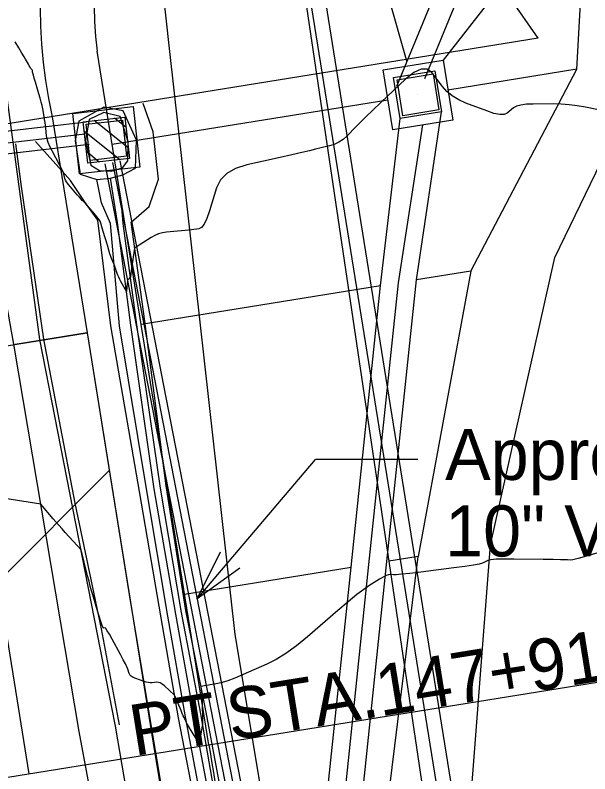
# Model space of a CAD drawing. Extents: x 2030588 to 2035216, y 462285 to 465007.
# Drawn here: x 2031264.56 to 2031296.08, y 464275.55 to 464317.16 of the extents above; entities that cross this region are included whole.
import ezdxf

# ---------------------------------------------------------------- set-up
doc = ezdxf.new("R2010")
doc.units = 0
for name, color, linetype in [('DR_P_Cells', 7, 'Continuous'), ('DR_P_Ditch', 7, 'Continuous'), ('DR_P_Drive_Pipe', 7, 'Continuous'), ('DR_X_Cells', 7, 'Continuous'), ('DR_X_Ditch', 7, 'Continuous'), ('DR_X_Storm_Sewer', 7, 'Continuous'), ('DT_P_Pavement_Surface', 7, 'Continuous'), ('DT_P_Slope_Break_Line', 7, 'Continuous'), ('DT_X_Contour_Minor', 7, 'Continuous'), ('GE_X_Alignment_100_Cardinal_Points', 7, 'Continuous'), ('GK_Drainage_Nodes', 7, 'Continuous'), ('MD_P_CONST_LIMITS', 7, 'Continuous'), ('MT_P_Temp_Road', 7, 'Continuous'), ('PV_P_EOP', 7, 'Continuous'), ('PV_P_Shoulder', 7, 'Continuous'), ('PV_X_EOP', 7, 'Continuous'), ('PV_X_Shoulder_Aggregate', 7, 'Continuous'), ('RW_X_Esmt_SH', 7, 'Continuous'), ('SV_X_Break_Lines', 7, 'Continuous'), ('SV_X_Text', 7, 'Continuous'), ('SV_X_Toe_of_Slope', 7, 'Continuous'), ('UT_X_Cable_TV', 7, 'Continuous'), ('UT_X_Electric', 7, 'Continuous'), ('UT_X_Telecom', 7, 'Continuous')]:
    doc.layers.add(name, color=color, linetype=linetype)

msp = doc.modelspace()

# ---------------------------------------------------------------- linework, layer by layer
at = {"layer": 'DR_P_Cells'}
for points in [[(2031284.745, 464314.169), (2031288.035, 464314.699), (2031288.566, 464311.409), (2031285.275, 464310.878)], [(2031285.315, 464313.748), (2031287.577, 464314.113), (2031287.942, 464311.851), (2031285.68, 464311.486)], [(2031285.509, 464313.617), (2031287.483, 464313.935), (2031287.802, 464311.961), (2031285.827, 464311.642)]]:
    msp.add_lwpolyline(points, close=True, dxfattribs=at)
at = {"layer": 'DR_P_Ditch'}
msp.add_lwpolyline([(2031284.892, 464242.767), (2031281.32, 464261.654), (2031283.968, 464287.035), (2031285.58, 464302.487), (2031286.92, 464311.143)], dxfattribs=at)
at = {"layer": 'DR_P_Drive_Pipe'}
for p, q in [((2031285.496, 464313.266), (2031292.582, 464330.451)), ((2031287.024, 464313.693), (2031293.738, 464329.975))]:
    msp.add_line(p, q, dxfattribs=at)
at = {"layer": 'DR_X_Cells'}
for p, q in [((2031270.759, 464309.885), (2031268.888, 464311.378)), ((2031270.633, 464311.009), (2031270.012, 464311.504)), ((2031270.297, 464309.231), (2031268.352, 464310.782)), ((2031269.172, 464309.104), (2031268.479, 464309.658)), ((2031269.479, 464309.004), (2031281.942, 464244.875)), ((2031270.297, 464309.163), (2031282.76, 464245.034))]:
    msp.add_line(p, q, dxfattribs=at)
for points in [[(2031268.089, 464308.458), (2031267.717, 464311.77), (2031271.029, 464312.143), (2031271.402, 464308.831)], [(2031268.549, 464309.034), (2031268.293, 464311.311), (2031270.57, 464311.567), (2031270.826, 464309.29)], [(2031268.677, 464309.195), (2031268.454, 464311.183), (2031270.441, 464311.406), (2031270.665, 464309.419)]]:
    msp.add_lwpolyline(points, close=True, dxfattribs=at)
for points in [[(2031268.463, 464311.299), (2031228.624, 464306.683), (2031220.262, 464304.833)], [(2031268.607, 464310.058), (2031228.832, 464305.449), (2031220.532, 464303.612)]]:
    msp.add_lwpolyline(points, dxfattribs=at)
at = {"layer": 'DR_X_Ditch'}
msp.add_lwpolyline([(2031283.585, 464238.805), (2031282.994, 464242.68), (2031282.457, 464245.05), (2031282.215, 464245.98), (2031281.153, 464249.314), (2031279.262, 464255.559), (2031277.89, 464260.044), (2031276.729, 464266.057), (2031276.13, 464269.315), (2031274.349, 464278.781), (2031273.365, 464284.3), (2031272.182, 464291.179), (2031270.91, 464300.165), (2031270.166, 464305.78), (2031269.924, 464307.279), (2031269.78, 464308.217)], dxfattribs=at)
at = {"layer": 'DR_X_Storm_Sewer'}
msp.add_line((2031269.888, 464309.084), (2031282.351, 464244.954), dxfattribs=at)
msp.add_lwpolyline([(2031220.397, 464304.222), (2031228.728, 464306.066), (2031268.535, 464310.679)], dxfattribs=at)
at = {"layer": 'DT_P_Pavement_Surface'}
msp.add_line((2031249.704, 464272.177), (2031269.72, 464292.193), dxfattribs=at)
msp.add_lwpolyline([(2031257.072, 464231.726), (2031252.323, 464256.477), (2031248.187, 464281.266), (2031245.799, 464296.073), (2031268.504, 464299.734), (2031270.891, 464284.927), (2031274.963, 464260.519), (2031278.406, 464242.26), (2031279.291, 464236.286)], dxfattribs=at)
at = {"layer": 'DT_P_Slope_Break_Line'}
for p, q in [((2031279.724, 464336.992), (2031286.045, 464314.597)), ((2031295.957, 464324.8), (2031288.035, 464314.699)), ((2031295.379, 464314.195), (2031295.957, 464324.8)), ((2031295.379, 464314.195), (2031288.3, 464313.054)), ((2031289.549, 464303.127), (2031295.379, 464314.195)), ((2031269.874, 464310.083), (2031285.01, 464312.523)), ((2031286.568, 464302.646), (2031287.942, 464311.851)), ((2031284.593, 464302.328), (2031285.68, 464311.486)), ((2031289.549, 464303.127), (2031286.568, 464302.646)), ((2031289.549, 464303.127), (2031286.663, 464287.469)), ((2031284.955, 464287.194), (2031286.568, 464302.646)), ((2031271.465, 464300.211), (2031284.593, 464302.328)), ((2031282.981, 464286.876), (2031284.593, 464302.328)), ((2031282.304, 464261.829), (2031284.955, 464287.194)), ((2031283.52, 464262.046), (2031286.663, 464287.469)), ((2031286.663, 464287.469), (2031285.06, 464287.211)), ((2031273.853, 464285.404), (2031282.981, 464286.876)), ((2031280.336, 464261.478), (2031282.981, 464286.876))]:
    msp.add_line(p, q, dxfattribs=at)
msp.add_lwpolyline([(2031275.186, 464277.134), (2031275.186, 464277.137), (2031269.052, 464315.179)], dxfattribs=at)
for centre, major_axis, start_param, end_param in [((2031291.052, 464317.932), (-14.795, 16.514), 6.08887, 7.247899), ((2032214.825, 464428.293), (-636.704, 707.385), 0.997445, 1.014591)]:
    msp.add_ellipse(centre, major_axis=major_axis, ratio=0.999987, start_param=start_param, end_param=end_param, dxfattribs=at)
at = {"layer": 'DT_X_Contour_Minor'}
for points in [[(2031297.094, 464311.851), (2031295.851, 464312.106), (2031295.391, 464312.189), (2031294.944, 464312.248), (2031294.51, 464312.283), (2031294.089, 464312.293), (2031292.982, 464312.288), (2031292.602, 464312.273), (2031292.294, 464312.233), (2031292.058, 464312.166), (2031291.893, 464312.073), (2031291.547, 464311.79), (2031291.38, 464311.718), (2031291.139, 464311.713), (2031290.823, 464311.775), (2031290.432, 464311.905), (2031289.29, 464312.34), (2031288.888, 464312.519), (2031288.537, 464312.729), (2031288.24, 464312.97), (2031287.994, 464313.242), (2031287.408, 464314.009), (2031287.154, 464314.202), (2031286.83, 464314.205), (2031286.435, 464314.018), (2031285.972, 464313.642), (2031284.642, 464312.384), (2031284.181, 464311.947), (2031283.797, 464311.578), (2031283.49, 464311.278), (2031283.259, 464311.046), (2031282.745, 464310.52), (2031282.542, 464310.338), (2031282.315, 464310.189), (2031282.066, 464310.072), (2031281.795, 464309.986), (2031281.042, 464309.802), (2031280.709, 464309.722), (2031280.275, 464309.621), (2031279.739, 464309.498), (2031279.103, 464309.355), (2031277.271, 464308.944), (2031276.652, 464308.75), (2031276.168, 464308.475), (2031275.819, 464308.121), (2031275.607, 464307.687), (2031275.22, 464306.423), (2031275.074, 464306.006), (2031274.927, 464305.703), (2031274.779, 464305.513), (2031274.63, 464305.437), (2031274.23, 464305.386), (2031274.07, 464305.367), (2031273.89, 464305.348), (2031273.69, 464305.329), (2031273.47, 464305.31), (2031272.858, 464305.261), (2031272.633, 464305.229), (2031272.417, 464305.169), (2031272.21, 464305.083), (2031272.012, 464304.969), (2031271.11, 464304.375), (2031271.013, 464303.757), (2031270.992, 464303.628), (2031270.974, 464303.506), (2031270.958, 464303.391), (2031270.943, 464303.284), (2031270.878, 464302.8), (2031270.765, 464302.685), (2031270.743, 464302.651), (2031270.725, 464302.6), (2031270.711, 464302.532), (2031270.701, 464302.445), (2031270.667, 464302.003), (2031270.361, 464302.554), (2031270.299, 464302.67), (2031270.244, 464302.783), (2031270.196, 464302.892), (2031270.156, 464302.998), (2031269.981, 464303.481), (2031269.843, 464303.818), (2031269.807, 464303.918), (2031269.757, 464304.07), (2031269.693, 464304.277), (2031269.616, 464304.537), (2031269.391, 464305.302), (2031269.316, 464305.555), (2031269.257, 464305.743), (2031269.214, 464305.864), (2031269.189, 464305.919), (2031269.143, 464305.977), (2031269.116, 464306.011), (2031269.067, 464306.07), (2031268.998, 464306.152), (2031268.908, 464306.259), (2031268.438, 464306.813), (2031268.365, 464306.879), (2031268.35, 464306.893), (2031268.334, 464306.907), (2031268.319, 464306.92), (2031268.303, 464306.934), (2031268.262, 464306.969), (2031268.231, 464307.001), (2031268.17, 464307.069), (2031268.078, 464307.173), (2031267.956, 464307.314), (2031267.588, 464307.739), (2031267.466, 464307.887), (2031267.374, 464308.013), (2031267.312, 464308.117), (2031267.282, 464308.198), (2031267.209, 464308.525), (2031266.584, 464309.721), (2031266.464, 464309.965), (2031266.374, 464310.184), (2031266.313, 464310.377), (2031266.282, 464310.545), (2031266.237, 464310.961), (2031266.219, 464311.117), (2031266.197, 464311.275), (2031266.172, 464311.435), (2031266.144, 464311.596), (2031266.066, 464312.027), (2031266.031, 464312.2), (2031265.985, 464312.392), (2031265.928, 464312.606), (2031265.86, 464312.84), (2031265.663, 464313.493), (2031265.599, 464313.71), (2031265.552, 464313.872), (2031265.523, 464313.978), (2031265.513, 464314.028), (2031265.509, 464314.09), (2031265.506, 464314.112), (2031265.498, 464314.134), (2031265.487, 464314.154), (2031265.471, 464314.173), (2031265.425, 464314.224), (2031265.403, 464314.253), (2031265.371, 464314.303), (2031265.329, 464314.375), (2031265.278, 464314.467), (2031265.128, 464314.741), (2031265.05, 464314.879), (2031264.928, 464315.085), (2031264.762, 464315.362), (2031264.552, 464315.707)], [(2031296.523, 464287.666), (2031295.902, 464287.484), (2031295.443, 464287.356), (2031295.145, 464287.282), (2031295.008, 464287.261), (2031294.86, 464287.276), (2031294.735, 464287.282), (2031294.472, 464287.289), (2031294.071, 464287.297), (2031293.533, 464287.305), (2031291.913, 464287.328), (2031291.368, 464287.329), (2031290.948, 464287.315), (2031290.653, 464287.287), (2031290.484, 464287.244), (2031290.198, 464287.109), (2031290.02, 464287.054), (2031289.698, 464286.991), (2031289.233, 464286.919), (2031288.624, 464286.839), (2031286.811, 464286.614), (2031286.207, 464286.541), (2031285.756, 464286.491), (2031285.458, 464286.463), (2031285.312, 464286.459), (2031285.128, 464286.479), (2031285.039, 464286.468), (2031284.913, 464286.421), (2031284.748, 464286.338), (2031284.545, 464286.219), (2031283.952, 464285.852), (2031283.68, 464285.664), (2031283.307, 464285.376), (2031282.833, 464284.987), (2031282.259, 464284.499), (2031280.594, 464283.062), (2031279.986, 464282.563), (2031279.412, 464282.147), (2031278.872, 464281.812), (2031278.365, 464281.558), (2031277.058, 464280.99), (2031276.605, 464280.799), (2031276.224, 464280.654), (2031275.915, 464280.553), (2031275.679, 464280.496), (2031274.747, 464280.338), (2031274.783, 464280.009), (2031274.791, 464279.928), (2031274.797, 464279.828), (2031274.803, 464279.707), (2031274.808, 464279.567), (2031274.82, 464279.165), (2031274.824, 464279.025), (2031274.827, 464278.907), (2031274.829, 464278.81), (2031274.829, 464278.735), (2031274.83, 464278.564), (2031274.83, 464278.504), (2031274.831, 464278.454), (2031274.832, 464278.413), (2031274.834, 464278.382), (2031274.842, 464278.259), (2031274.83, 464278.263), (2031274.825, 464278.244), (2031274.813, 464278.183), (2031274.796, 464278.082), (2031274.772, 464277.94), (2031274.65, 464277.183), (2031274.579, 464277.302), (2031274.555, 464277.344), (2031274.513, 464277.416), (2031274.452, 464277.519), (2031274.374, 464277.653), (2031273.964, 464278.351), (2031273.952, 464278.378), (2031273.947, 464278.388), (2031273.937, 464278.407), (2031273.923, 464278.434), (2031273.905, 464278.47), (2031273.849, 464278.578), (2031273.822, 464278.636), (2031273.78, 464278.728), (2031273.725, 464278.855), (2031273.656, 464279.017), (2031273.303, 464279.854), (2031272.742, 464280.37), (2031272.625, 464280.465), (2031272.516, 464280.53), (2031272.415, 464280.564), (2031272.321, 464280.569), (2031272.079, 464280.54), (2031271.981, 464280.537), (2031271.866, 464280.551), (2031271.734, 464280.581), (2031271.586, 464280.627), (2031271.169, 464280.774), (2031271.028, 464280.833), (2031270.921, 464280.9), (2031270.845, 464280.975), (2031270.802, 464281.058), (2031270.731, 464281.29), (2031270.687, 464281.406), (2031270.606, 464281.578), (2031270.489, 464281.806), (2031270.336, 464282.092), (2031269.88, 464282.928), (2031269.728, 464283.202), (2031269.611, 464283.397), (2031269.53, 464283.513), (2031269.486, 464283.551), (2031269.415, 464283.545), (2031269.387, 464283.558), (2031269.357, 464283.603), (2031269.323, 464283.68), (2031269.287, 464283.787), (2031269.11, 464284.362), (2031268.813, 464285.365), (2031268.748, 464285.591), (2031268.679, 464285.841), (2031268.607, 464286.113), (2031268.532, 464286.408), (2031268.172, 464287.839), (2031267.306, 464288.79), (2031267.125, 464288.989), (2031266.955, 464289.181), (2031266.794, 464289.363), (2031266.644, 464289.538), (2031265.965, 464290.332), (2031260.371, 464291.215)]]:
    msp.add_lwpolyline(points, dxfattribs=at)
at = {"layer": 'GE_X_Alignment_100_Cardinal_Points'}
msp.add_line((2031257.417, 464274.275), (2031301.838, 464281.437), dxfattribs=at)
at = {"layer": 'GK_Drainage_Nodes'}
for p, q in [((2031286.39, 464314.434), (2031286.39, 464314.434)), ((2031286.496, 464313.776), (2031286.496, 464313.776)), ((2031285.668, 464312.629), (2031285.668, 464312.629)), ((2031286.655, 464312.789), (2031286.655, 464312.789)), ((2031286.655, 464312.789), (2031286.655, 464312.789)), ((2031286.655, 464312.789), (2031286.655, 464312.789)), ((2031287.642, 464312.948), (2031287.642, 464312.948)), ((2031286.814, 464311.801), (2031286.814, 464311.801)), ((2031269.448, 464311.294), (2031269.448, 464311.294)), ((2031286.92, 464311.143), (2031286.92, 464311.143)), ((2031271.215, 464310.487), (2031271.215, 464310.487)), ((2031267.903, 464310.114), (2031267.903, 464310.114)), ((2031268.566, 464310.189), (2031268.566, 464310.189)), ((2031269.559, 464310.301), (2031269.559, 464310.301)), ((2031269.559, 464310.301), (2031269.559, 464310.301)), ((2031269.559, 464310.301), (2031269.559, 464310.301)), ((2031270.553, 464310.412), (2031270.553, 464310.412)), ((2031269.671, 464309.307), (2031269.671, 464309.307))]:
    msp.add_line(p, q, dxfattribs=at)
at = {"layer": 'MD_P_CONST_LIMITS'}
msp.add_lwpolyline([(2031304.871, 464099.462), (2031318.532, 464105.655), (2031311.904, 464118.546), (2031304.38, 464141.463), (2031297.225, 464164.67), (2031295.574, 464189.665), (2031297.675, 464215.284), (2031293.386, 464239.179), (2031288.691, 464262.969), (2031290.634, 464288.11), (2031294.17, 464303.872), (2031299.488, 464314.858)], dxfattribs=at)
at = {"layer": 'MT_P_Temp_Road'}
for points in [[(2031268.504, 464299.734), (2031272.224, 464276.66), (2031272.225, 464276.658)], [(2031261.594, 464298.62), (2031265.314, 464275.547), (2031265.314, 464275.546)]]:
    msp.add_lwpolyline(points, dxfattribs=at)
msp.add_ellipse((2032214.825, 464428.293), major_axis=(-637.035, 711.12), ratio=0.999987, start_param=0.999804, end_param=1.036412, dxfattribs=at)
at = {"layer": 'PV_P_EOP'}
for q in [(2031275.613, 464341.393), (2031262.643, 464310.954)]:
    msp.add_line((2031293.243, 464315.898), q, dxfattribs=at)
msp.add_ellipse((2031293.243, 464315.898), major_axis=(-20.684, 23.086), ratio=0.999987, start_param=6.157653, end_param=7.283599, dxfattribs=at)
at = {"layer": 'PV_P_Shoulder'}
for p, q in [((2031266.592, 464311.591), (2031268.504, 464299.734)), ((2031268.504, 464299.734), (2031264.555, 464299.097))]:
    msp.add_line(p, q, dxfattribs=at)
msp.add_ellipse((2031293.928, 464317.64), major_axis=(-18.684, 20.851), ratio=0.999987, start_param=6.213097, end_param=7.341063, dxfattribs=at)
at = {"layer": 'PV_X_EOP'}
msp.add_lwpolyline([(2031353.162, 464035.71), (2031341.874, 464052.676), (2031332.716, 464067.744), (2031330.521, 464071.931), (2031322.023, 464088.196), (2031314.108, 464105.099), (2031307.351, 464122.147), (2031301.267, 464138.466), (2031296.143, 464154.308), (2031290.945, 464171.988), (2031286.324, 464189.894), (2031281.443, 464210.564), (2031280.322, 464215.544), (2031275.666, 464237.435), (2031271.643, 464258.648), (2031268.07, 464277.87), (2031264.482, 464299.113), (2031261, 464318.439), (2031259.92, 464324.373)], dxfattribs=at)
at = {"layer": 'PV_X_Shoulder_Aggregate'}
msp.add_lwpolyline([(2031277.635, 464237.84), (2031273.355, 464258.914), (2031270.066, 464278.166), (2031265.916, 464299.362), (2031263.298, 464318.606), (2031263.318, 464322.998), (2031263.199, 464325.189), (2031262.878, 464328.279), (2031260.848, 464338.194), (2031257.913, 464356.817), (2031254.754, 464370.404), (2031253.155, 464376.691), (2031250.944, 464380.086), (2031250.391, 464381.285), (2031248.022, 464396.129), (2031244.492, 464415.82), (2031241.204, 464437.394)], dxfattribs=at)
at = {"layer": 'RW_X_Esmt_SH'}
msp.add_line((2031294.07, 464235.295), (2031222.33, 464681.217), dxfattribs=at)
at = {"layer": 'SV_X_Break_Lines'}
for points in [[(2031286.097, 464239.508), (2031285.759, 464240.73), (2031284.876, 464242.786), (2031284.735, 464244.273), (2031284.376, 464245.449), (2031284.16, 464245.982), (2031283.312, 464246.903), (2031281.793, 464249.396), (2031279.768, 464255.603), (2031278.404, 464260.171), (2031277.616, 464266.141), (2031276.809, 464269.456), (2031275.029, 464278.928), (2031273.911, 464284.508), (2031272.831, 464291.342), (2031271.661, 464300.379), (2031270.912, 464305.814), (2031271.898, 464306.671), (2031272.412, 464308.162), (2031272.135, 464310.757), (2031271.572, 464312.32)], [(2031270.284, 464278.23), (2031269.29, 464283.499), (2031267.855, 464290.387), (2031266.131, 464299.394), (2031265.263, 464305.263), (2031264.909, 464307.769), (2031264.599, 464310.103)], [(2031282.947, 464231.538), (2031283.186, 464232.985), (2031283.1, 464233.71), (2031282.533, 464238.56), (2031281.555, 464242.327), (2031281.352, 464244.842), (2031281.407, 464245.871), (2031280.309, 464249.266), (2031278.451, 464255.467), (2031277.014, 464259.841), (2031275.774, 464265.918), (2031275.32, 464269.267), (2031273.515, 464278.626), (2031272.571, 464284.096), (2031271.385, 464291.028), (2031269.801, 464300.113), (2031269.085, 464305.912), (2031268.352, 464306.933), (2031267.595, 464308.094), (2031265.679, 464310.232)]]:
    msp.add_lwpolyline(points, dxfattribs=at)
for points in [[(2031270.482, 464311.911), (2031269.423, 464312.111), (2031268.043, 464311.34), (2031267.84, 464310.288), (2031268.115, 464308.438), (2031269.04, 464308.145), (2031269.78, 464308.217), (2031270.469, 464308.398), (2031271.152, 464308.776), (2031271.208, 464310.296)], [(2031270.311, 464311.594), (2031269.423, 464311.816), (2031268.617, 464311.443), (2031268.421, 464310.285), (2031268.713, 464308.937), (2031269.186, 464308.632), (2031269.816, 464308.606), (2031270.445, 464308.796), (2031270.731, 464309.166), (2031270.75, 464310.216)]]:
    msp.add_lwpolyline(points, close=True, dxfattribs=at)
at = {"layer": 'SV_X_Text'}
for p in [(2031274.541, 464285.143), (2031286.642, 464292.783)]:
    msp.add_line(p, (2031281.042, 464292.783), dxfattribs=at)
msp.add_lwpolyline([(2031276.888, 464286.821), (2031274.541, 464285.143), (2031275.822, 464287.729)], dxfattribs=at)
at = {"layer": 'SV_X_Toe_of_Slope'}
for points in [[(2031282.916, 464238.677), (2031282.163, 464242.433), (2031281.929, 464245.048), (2031281.934, 464245.459), (2031281.795, 464245.93), (2031280.749, 464249.277), (2031278.778, 464255.438), (2031277.519, 464259.946), (2031276.207, 464265.98), (2031275.683, 464269.262), (2031273.904, 464278.669), (2031272.935, 464284.196), (2031271.786, 464291.063), (2031270.288, 464300.115), (2031269.777, 464305.729), (2031269.297, 464306.867), (2031269.04, 464308.145)], [(2031284.884, 464239.166), (2031284.485, 464241.32), (2031284.315, 464242.851), (2031284.052, 464244.087), (2031283.711, 464245.007), (2031282.951, 464245.359), (2031282.593, 464246.172), (2031281.431, 464249.391), (2031279.578, 464255.544), (2031278.208, 464260.158), (2031277.226, 464266.073), (2031276.39, 464269.368), (2031274.742, 464278.836), (2031273.689, 464284.396), (2031272.521, 464291.221), (2031271.239, 464300.178), (2031270.473, 464305.735), (2031270.417, 464306.417)]]:
    msp.add_lwpolyline(points, dxfattribs=at)
at = {"layer": 'UT_X_Cable_TV'}
msp.add_lwpolyline([(2031238.795, 464585.928), (2031247.129, 464533.781), (2031254.05, 464490.196), (2031262.253, 464438.839), (2031269.698, 464392.26), (2031276.53, 464349.484), (2031283.448, 464306.226), (2031289.883, 464266.155)], dxfattribs=at)
at = {"layer": 'UT_X_Electric'}
msp.add_lwpolyline([(2031221.843, 464713.466), (2031231.941, 464645.283), (2031244.284, 464562.24), (2031252.852, 464504.34), (2031260, 464456.218), (2031264.868, 464423.288), (2031269.313, 464393.306), (2031274.036, 464361.48), (2031280.969, 464314.78), (2031288.221, 464265.917), (2031292.226, 464240.822), (2031300.292, 464190.304), (2031337.855, 463955.944)], dxfattribs=at)
at = {"layer": 'UT_X_Telecom'}
msp.add_lwpolyline([(2031285.421, 464261.062), (2031282.829, 464263.075), (2031280.244, 464267.275), (2031278.637, 464271.132), (2031276.619, 464283.186), (2031273.03, 464315.325), (2031271.839, 464326.162), (2031274.513, 464334.072), (2031278.515, 464339.425), (2031283.376, 464343.379), (2031302.405, 464353.607), (2031313.884, 464359.383), (2031347.997, 464374.285), (2031378.364, 464389.658), (2031390.118, 464394.606)], dxfattribs=at)

# ---------------------------------------------------------------- texts
at = {"layer": 'GE_X_Alignment_100_Cardinal_Points'}
for s, p in [('147+91.63', (2031284.588, 464278.693)), (' STA. ', (2031275.385, 464277.21)), ('PT', (2031271.09, 464276.517))]:
    msp.add_text(s, height=2.7997, rotation=9.1587, dxfattribs=at).set_placement(p)
at = {"layer": 'SV_X_Text'}
for s, height, p in [('Approximate location of', 2.79972, (2031288.147, 464291.668)), ('10" VCP ', 2.7997, (2031288.147, 464287.469))]:
    msp.add_text(s, height=height, rotation=359.9993, dxfattribs=at).set_placement(p)

doc.saveas('drawing.dxf')
